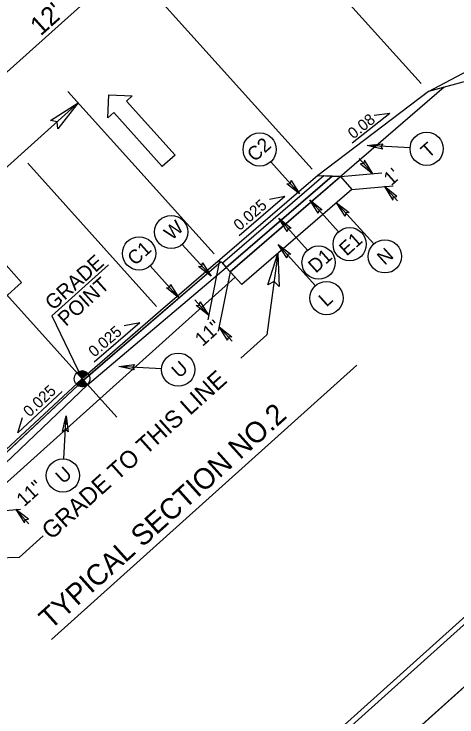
# Model space of a CAD drawing. Extents: x 2488411 to 2488707, y 383669 to 383962.
# Drawn here: x 2488617.46 to 2488643.06, y 383804.17 to 383844.82 of the extents above; entities that cross this region are included whole.
import ezdxf

# ---------------------------------------------------------------- set-up
doc = ezdxf.new("R2010")
doc.units = 0
for name, color, linetype in [('Old_Level_19', 7, 'Continuous'), ('Old_Level_21', 7, 'Continuous'), ('Old_Level_44', 7, 'Continuous'), ('Prop Dimension', 7, 'Continuous'), ('Prop DSN Text', 7, 'Continuous'), ('Prop Paint Stripe', 7, 'Continuous'), ('Prop Rip Rap Related Quantities Text', 7, 'Continuous'), ('Prop Roadway Profile Bench Mark Info Text', 7, 'Continuous'), ('Prop ROW RW Lines', 7, 'Continuous'), ('Prop XS SE Text', 7, 'Continuous'), ('Sheet Cutting Line CELL', 7, 'Continuous'), ('Sheet Data Field CELL', 7, 'Continuous'), ('Sheet Data Text CELL', 7, 'Continuous'), ('Sheet Plan CELL', 7, 'Continuous'), ('Sheet Sticker Incomplete CELL', 7, 'Continuous'), ('Sheet Sticker Preliminary CELL', 7, 'Continuous'), ('Sheet Symbology CELL', 7, 'Continuous'), ('Sheet Title CELL', 7, 'Continuous'), ('Typical Terminator CELL', 7, 'Continuous'), ('Typical Text Centerline CELL', 7, 'Continuous'), ('Typical Text ID Circle CELL', 7, 'Continuous')]:
    doc.layers.add(name, color=color, linetype=linetype)

msp = doc.modelspace()

# ---------------------------------------------------------------- linework, layer by layer
at = {"layer": 'Old_Level_19'}
msp.add_lwpolyline([(2488619.231, 383961.604), (2488468.948, 383826.508), (2488557.194, 383728.341), (2488707.477, 383863.438)], close=True, dxfattribs=at)
at = {"layer": 'Old_Level_21'}
msp.add_lwpolyline([(2488620.631, 383959.24), (2488471.909, 383825.547), (2488556.553, 383731.388), (2488705.275, 383865.081)], close=True, dxfattribs=at)
at = {"layer": 'Prop Dimension'}
for p, q in [((2488632.709, 383830.977), (2488632.073, 383826.262)), ((2488619.64, 383827.369), (2488622.913, 383830.311)), ((2488619.64, 383827.369), (2488621.392, 383823.728)), ((2488630.578, 383824.919), (2488632.073, 383826.262)), ((2488617.748, 383813.385), (2488619.151, 383814.647)), ((2488617.748, 383813.385), (2488612.992, 383813.253))]:
    msp.add_line(p, q, dxfattribs=at)
at = {"layer": 'Prop DSN Text'}
for p, q in [((2488640.35, 383837.081), (2488637.868, 383837.212)), ((2488632.299, 383836.276), (2488633.961, 383834.428)), ((2488636.216, 383832.221), (2488634.554, 383834.069)), ((2488638.253, 383831.522), (2488636.106, 383833.91)), ((2488634.423, 383831.16), (2488632.762, 383833.009)), ((2488627.186, 383831.501), (2488628.847, 383829.653)), ((2488634.879, 383829.11), (2488632.732, 383831.498)), ((2488625.329, 383830.262), (2488626.991, 383828.414)), ((2488625.991, 383824.306), (2488623.509, 383824.437)), ((2488620.335, 383819.093), (2488620.468, 383821.576))]:
    msp.add_line(p, q, dxfattribs=at)
for centre in [(2488631.656, 383836.991), (2488641.31, 383837.029), (2488626.543, 383832.216), (2488636.859, 383831.506), (2488624.687, 383830.977), (2488638.895, 383830.807), (2488635.066, 383830.445), (2488635.521, 383828.395), (2488626.951, 383824.254), (2488620.284, 383818.133)]:
    msp.add_circle(centre, 0.962, dxfattribs=at)
at = {"layer": 'Prop Paint Stripe'}
for points in [[(2488638.758, 383837.01), (2488637.868, 383837.212), (2488638.78, 383837.324), (2488638.657, 383837.17)], [(2488637.484, 383836.153), (2488638.201, 383835.587), (2488637.715, 383836.367), (2488637.673, 383836.175)], [(2488633.474, 383835.201), (2488633.961, 383834.428), (2488633.237, 383834.994), (2488633.433, 383835.015)], [(2488639.586, 383834.278), (2488638.869, 383834.844), (2488639.355, 383834.064), (2488639.398, 383834.256)], [(2488635.041, 383833.296), (2488634.554, 383834.069), (2488635.278, 383833.503), (2488635.082, 383833.482)], [(2488636.592, 383833.137), (2488636.106, 383833.91), (2488636.83, 383833.344), (2488636.634, 383833.323)], [(2488633.248, 383832.236), (2488632.762, 383833.009), (2488633.486, 383832.442), (2488633.29, 383832.421)], [(2488633.218, 383830.725), (2488632.732, 383831.498), (2488633.456, 383830.932), (2488633.26, 383830.911)], [(2488628.361, 383830.426), (2488628.847, 383829.653), (2488628.123, 383830.219), (2488628.319, 383830.24)], [(2488626.505, 383829.187), (2488626.991, 383828.414), (2488626.267, 383828.98), (2488626.463, 383829.002)], [(2488628.222, 383828.173), (2488628.709, 383827.4), (2488627.985, 383827.966), (2488628.18, 383827.988)], [(2488629.803, 383825.951), (2488629.317, 383826.723), (2488630.041, 383826.157), (2488629.845, 383826.136)], [(2488624.4, 383824.235), (2488623.509, 383824.437), (2488624.421, 383824.549), (2488624.298, 383824.396)], [(2488620.265, 383820.685), (2488620.468, 383821.576), (2488620.579, 383820.663), (2488620.426, 383820.787)], [(2488618.289, 383815.6), (2488617.572, 383816.166), (2488618.058, 383815.386), (2488618.101, 383815.578)]]:
    msp.add_lwpolyline(points, close=True, dxfattribs=at)
at = {"layer": 'Prop Rip Rap Related Quantities Text'}
for p, q in [((2488642.314, 383840.591), (2488629.949, 383829.915)), ((2488635.013, 383835.489), (2488625.932, 383827.648)), ((2488635.373, 383835.47), (2488629.508, 383830.406)), ((2488635.849, 383835.445), (2488629.729, 383830.16)), ((2488635.013, 383835.489), (2488636.325, 383835.42)), ((2488636.325, 383835.42), (2488636.993, 383834.676)), ((2488636.993, 383834.676), (2488630.618, 383829.171)), ((2488629.424, 383830.499), (2488621.473, 383823.634)), ((2488629.729, 383830.16), (2488629.424, 383830.499)), ((2488629.949, 383829.915), (2488630.618, 383829.171)), ((2488625.932, 383827.648), (2488621.392, 383823.728)), ((2488613.805, 383816.458), (2488621.477, 383823.637)), ((2488617.012, 383819.63), (2488621.392, 383823.728))]:
    msp.add_line(p, q, dxfattribs=at)
at = {"layer": 'Prop Roadway Profile Bench Mark Info Text'}
for p, q in [((2488639.183, 383839.079), (2488637.001, 383837.35)), ((2488639.183, 383839.079), (2488638.278, 383838.946)), ((2488633.117, 383834.277), (2488630.477, 383831.998)), ((2488633.117, 383834.277), (2488632.218, 383834.105)), ((2488624.729, 383826.96), (2488622.089, 383824.682)), ((2488624.729, 383826.96), (2488623.83, 383826.789)), ((2488617.674, 383820.603), (2488620.233, 383822.998)), ((2488617.674, 383820.603), (2488617.94, 383821.479))]:
    msp.add_line(p, q, dxfattribs=at)
at = {"layer": 'Prop ROW RW Lines'}
for p, q in [((2488622.886, 383838.826), (2488622.946, 383840.151)), ((2488622.946, 383840.151), (2488624.291, 383840.09)), ((2488624.291, 383840.09), (2488623.957, 383839.789)), ((2488623.957, 383839.789), (2488626.764, 383836.665)), ((2488623.22, 383839.127), (2488622.886, 383838.826)), ((2488626.028, 383836.004), (2488623.22, 383839.127)), ((2488626.764, 383836.665), (2488626.028, 383836.004)), ((2488617.895, 383829.288), (2488617.004, 383830.302)), ((2488616.904, 383828.416), (2488617.895, 383829.288))]:
    msp.add_line(p, q, dxfattribs=at)
at = {"layer": 'Prop XS SE Text'}
msp.add_line((2488557.194, 383728.341), (2488707.477, 383863.438), dxfattribs=at)
at = {"layer": 'Sheet Cutting Line CELL'}
msp.add_lwpolyline([(2488619.72, 383958.009), (2488485.857, 383837.674), (2488570.092, 383743.97), (2488703.955, 383864.305)], close=True, dxfattribs=at)
at = {"layer": 'Sheet Data Field CELL'}
for p, q in [((2488635.373, 383835.47), (2488629.508, 383830.406)), ((2488629.729, 383830.16), (2488635.849, 383835.445)), ((2488635.849, 383835.445), (2488635.373, 383835.47)), ((2488629.508, 383830.406), (2488629.729, 383830.16))]:
    msp.add_line(p, q, dxfattribs=at)
at = {"layer": 'Sheet Data Text CELL'}
msp.add_line((2488619.617, 383808.643), (2488637.267, 383824.51), dxfattribs=at)
at = {"layer": 'Sheet Plan CELL'}
for p, q in [((2488641.407, 383840.341), (2488648.692, 383844.202)), ((2488653.851, 383843.766), (2488641.407, 383840.341))]:
    msp.add_line(p, q, dxfattribs=at)
at = {"layer": 'Sheet Sticker Incomplete CELL'}
msp.add_line((2488641.407, 383840.341), (2488635.013, 383835.489), dxfattribs=at)
at = {"layer": 'Sheet Sticker Preliminary CELL'}
for points in [[(2488619.558, 383838.671), (2488621.168, 383839.684), (2488619.988, 383838.176), (2488619.944, 383838.584)], [(2488638.331, 383837.107), (2488637.868, 383837.212), (2488638.343, 383837.271), (2488638.278, 383837.19)], [(2488633.707, 383834.83), (2488633.961, 383834.428), (2488633.584, 383834.723), (2488633.686, 383834.734)], [(2488634.808, 383833.667), (2488634.554, 383834.069), (2488634.931, 383833.775), (2488634.829, 383833.763)], [(2488633.015, 383832.606), (2488632.762, 383833.009), (2488633.139, 383832.714), (2488633.037, 383832.703)], [(2488632.138, 383829.162), (2488632.709, 383830.977), (2488632.787, 383829.064), (2488632.489, 383829.346)], [(2488628.594, 383830.055), (2488628.847, 383829.653), (2488628.47, 383829.948), (2488628.572, 383829.959)], [(2488626.738, 383828.817), (2488626.991, 383828.414), (2488626.614, 383828.709), (2488626.716, 383828.72)], [(2488623.973, 383824.332), (2488623.509, 383824.437), (2488623.984, 383824.496), (2488623.92, 383824.416)], [(2488620.362, 383821.112), (2488620.468, 383821.576), (2488620.526, 383821.101), (2488620.446, 383821.165)]]:
    msp.add_lwpolyline(points, close=True, dxfattribs=at)
at = {"layer": 'Sheet Symbology CELL'}
for p, q in [((2488635.849, 383835.445), (2488629.729, 383830.16)), ((2488632.911, 383832.472), (2488636.325, 383835.42)), ((2488636.325, 383835.42), (2488635.849, 383835.445)), ((2488629.949, 383829.915), (2488632.911, 383832.472)), ((2488632.911, 383832.472), (2488632.911, 383832.472)), ((2488629.729, 383830.16), (2488629.424, 383830.499)), ((2488629.424, 383830.499), (2488629.424, 383830.499)), ((2488621.702, 383823.383), (2488629.729, 383830.16)), ((2488629.729, 383830.16), (2488629.949, 383829.915)), ((2488614.111, 383816.121), (2488621.702, 383823.383))]:
    msp.add_line(p, q, dxfattribs=at)
for points in [[(2488632.911, 383832.472), (2488632.911, 383832.472)], [(2488629.424, 383830.499), (2488621.477, 383823.637), (2488621.559, 383823.543)], [(2488621.559, 383823.543), (2488621.477, 383823.637), (2488613.805, 383816.458)]]:
    msp.add_lwpolyline(points, dxfattribs=at)
at = {"layer": 'Sheet Title CELL'}
for p, q in [((2488640.989, 383840.807), (2488629.385, 383853.715)), ((2488591.299, 383818.326), (2488629.958, 383853.078)), ((2488634.692, 383835.847), (2488621.618, 383850.39)), ((2488629.023, 383830.945), (2488620.574, 383840.344)), ((2488605.55, 383825.645), (2488621.168, 383839.684)), ((2488638.201, 383835.587), (2488637.406, 383836.472)), ((2488625.694, 383827.913), (2488618.251, 383836.192)), ((2488636.325, 383835.42), (2488638.714, 383835.633)), ((2488636.993, 383834.676), (2488639.383, 383834.89)), ((2488639.616, 383834.013), (2488638.869, 383834.844)), ((2488629.341, 383830.592), (2488628.655, 383827.127)), ((2488629.949, 383829.915), (2488629.267, 383826.471)), ((2488628.709, 383827.4), (2488627.913, 383828.285)), ((2488630.064, 383825.892), (2488629.317, 383826.723)), ((2488614.332, 383815.876), (2488617.829, 383816.189)), ((2488618.32, 383815.335), (2488617.572, 383816.166))]:
    msp.add_line(p, q, dxfattribs=at)
at = {"layer": 'Typical Terminator CELL'}
msp.add_line((2488623.395, 383821.5), (2488613.727, 383832.255), dxfattribs=at)
at = {"layer": 'Typical Text Centerline CELL'}
for p, q in [((2488621.093, 383824.062), (2488621.392, 383823.728)), ((2488621.392, 383823.728), (2488621.093, 383824.062)), ((2488621.725, 383824.028), (2488621.392, 383823.728)), ((2488621.059, 383823.429), (2488621.392, 383823.728)), ((2488621.392, 383823.728), (2488621.691, 383823.396))]:
    msp.add_line(p, q, dxfattribs=at)
for points in [[(2488621.397, 383823.733), (2488621.098, 383824.066), (2488621.098, 383824.066)], [(2488621.403, 383823.739), (2488621.104, 383824.072)], [(2488621.41, 383823.745), (2488621.112, 383824.077)], [(2488621.417, 383823.751), (2488621.118, 383824.083)], [(2488621.423, 383823.757), (2488621.126, 383824.088)], [(2488621.43, 383823.763), (2488621.133, 383824.094)], [(2488621.437, 383823.769), (2488621.14, 383824.099)], [(2488621.443, 383823.775), (2488621.148, 383824.103)], [(2488621.45, 383823.781), (2488621.156, 383824.109)], [(2488621.457, 383823.787), (2488621.163, 383824.113)], [(2488621.463, 383823.793), (2488621.171, 383824.118)], [(2488621.47, 383823.799), (2488621.179, 383824.122)], [(2488621.477, 383823.805), (2488621.187, 383824.127)], [(2488621.483, 383823.811), (2488621.196, 383824.13)], [(2488621.49, 383823.817), (2488621.204, 383824.135)], [(2488621.497, 383823.823), (2488621.213, 383824.139)], [(2488621.503, 383823.829), (2488621.221, 383824.142)], [(2488621.51, 383823.835), (2488621.23, 383824.146)], [(2488621.517, 383823.841), (2488621.239, 383824.149)], [(2488621.523, 383823.847), (2488621.249, 383824.152)], [(2488621.53, 383823.853), (2488621.258, 383824.155)], [(2488621.537, 383823.859), (2488621.267, 383824.158)], [(2488621.543, 383823.865), (2488621.277, 383824.161)], [(2488621.55, 383823.871), (2488621.287, 383824.164)], [(2488621.557, 383823.877), (2488621.297, 383824.166)], [(2488621.563, 383823.883), (2488621.307, 383824.168)], [(2488621.57, 383823.889), (2488621.317, 383824.17)], [(2488621.577, 383823.895), (2488621.328, 383824.171)], [(2488621.583, 383823.901), (2488621.339, 383824.173)], [(2488621.59, 383823.907), (2488621.349, 383824.174)], [(2488621.597, 383823.913), (2488621.36, 383824.175)], [(2488621.603, 383823.919), (2488621.372, 383824.176)], [(2488621.61, 383823.925), (2488621.384, 383824.176)], [(2488621.616, 383823.931), (2488621.396, 383824.176)], [(2488621.623, 383823.937), (2488621.408, 383824.176)], [(2488621.63, 383823.943), (2488621.42, 383824.176)], [(2488621.636, 383823.949), (2488621.434, 383824.174)], [(2488621.643, 383823.955), (2488621.447, 383824.173)], [(2488621.65, 383823.961), (2488621.461, 383824.171)], [(2488621.656, 383823.966), (2488621.475, 383824.168)], [(2488621.663, 383823.972), (2488621.49, 383824.166)], [(2488621.67, 383823.978), (2488621.505, 383824.162)], [(2488621.676, 383823.984), (2488621.521, 383824.158)], [(2488621.683, 383823.99), (2488621.538, 383824.152)], [(2488621.69, 383823.996), (2488621.556, 383824.145)], [(2488621.696, 383824.002), (2488621.575, 383824.137)], [(2488621.703, 383824.008), (2488621.596, 383824.127)], [(2488621.71, 383824.014), (2488621.621, 383824.113)], [(2488621.716, 383824.02), (2488621.649, 383824.096)], [(2488621.723, 383824.026), (2488621.69, 383824.063)], [(2488621.105, 383823.385), (2488621.062, 383823.433)], [(2488621.142, 383823.357), (2488621.069, 383823.439)], [(2488621.17, 383823.34), (2488621.076, 383823.445)], [(2488621.193, 383823.328), (2488621.082, 383823.451)], [(2488621.213, 383823.318), (2488621.089, 383823.456)], [(2488621.233, 383823.31), (2488621.096, 383823.462)], [(2488621.25, 383823.304), (2488621.102, 383823.468)], [(2488621.267, 383823.299), (2488621.109, 383823.474)], [(2488621.283, 383823.295), (2488621.116, 383823.48)], [(2488621.298, 383823.291), (2488621.122, 383823.486)], [(2488621.313, 383823.288), (2488621.129, 383823.492)], [(2488621.327, 383823.286), (2488621.136, 383823.498)], [(2488621.341, 383823.284), (2488621.142, 383823.504)], [(2488621.354, 383823.283), (2488621.149, 383823.51)], [(2488621.366, 383823.282), (2488621.156, 383823.516)], [(2488621.379, 383823.281), (2488621.162, 383823.522)], [(2488621.391, 383823.281), (2488621.169, 383823.528)], [(2488621.403, 383823.281), (2488621.176, 383823.534)], [(2488621.415, 383823.281), (2488621.182, 383823.54)], [(2488621.426, 383823.282), (2488621.189, 383823.546)], [(2488621.437, 383823.284), (2488621.196, 383823.552)], [(2488621.448, 383823.285), (2488621.202, 383823.558)], [(2488621.459, 383823.286), (2488621.209, 383823.564)], [(2488621.47, 383823.288), (2488621.216, 383823.57)], [(2488621.48, 383823.29), (2488621.222, 383823.576)], [(2488621.49, 383823.292), (2488621.229, 383823.582)], [(2488621.5, 383823.294), (2488621.236, 383823.588)], [(2488621.51, 383823.297), (2488621.242, 383823.594)], [(2488621.519, 383823.3), (2488621.249, 383823.6)], [(2488621.528, 383823.303), (2488621.256, 383823.606)], [(2488621.537, 383823.306), (2488621.262, 383823.612)], [(2488621.547, 383823.309), (2488621.269, 383823.618)], [(2488621.556, 383823.312), (2488621.276, 383823.624)], [(2488621.565, 383823.316), (2488621.282, 383823.63)], [(2488621.573, 383823.319), (2488621.289, 383823.636)], [(2488621.582, 383823.323), (2488621.295, 383823.642)], [(2488621.59, 383823.328), (2488621.302, 383823.648)], [(2488621.599, 383823.331), (2488621.309, 383823.654)], [(2488621.607, 383823.336), (2488621.315, 383823.66)], [(2488621.615, 383823.34), (2488621.322, 383823.666)], [(2488621.623, 383823.345), (2488621.329, 383823.672)], [(2488621.631, 383823.349), (2488621.335, 383823.678)], [(2488621.638, 383823.355), (2488621.342, 383823.684)], [(2488621.645, 383823.36), (2488621.349, 383823.69)], [(2488621.653, 383823.365), (2488621.355, 383823.696)], [(2488621.66, 383823.37), (2488621.362, 383823.702)], [(2488621.667, 383823.376), (2488621.369, 383823.708)], [(2488621.674, 383823.382), (2488621.375, 383823.714)], [(2488621.681, 383823.387), (2488621.382, 383823.72)], [(2488621.688, 383823.393), (2488621.688, 383823.393), (2488621.389, 383823.726)]]:
    msp.add_lwpolyline(points, dxfattribs=at)
msp.add_circle((2488621.392, 383823.729), 0.448, dxfattribs=at)
for start, end in [(41.9443, 131.9443), (221.9443, 311.9443)]:
    msp.add_arc((2488621.392, 383823.729), 0.448, start, end, dxfattribs=at)
at = {"layer": 'Typical Text ID Circle CELL'}
for p, q in [((2488621.702, 383823.383), (2488629.729, 383830.16)), ((2488630.234, 383829.598), (2488629.729, 383830.16)), ((2488614.617, 383815.559), (2488630.234, 383829.598)), ((2488614.111, 383816.121), (2488621.702, 383823.383))]:
    msp.add_line(p, q, dxfattribs=at)

# ---------------------------------------------------------------- texts
at = {"layer": 'Old_Level_44'}
for s, p in [('C2', (2488631.371, 383836.235)), ('T', (2488641.413, 383836.445)), ('W', (2488626.574, 383831.699)), ('E1', (2488636.689, 383830.788)), ('C1', (2488624.453, 383830.235)), ('D1', (2488634.901, 383829.799)), ('N', (2488638.888, 383830.257)), ('L', (2488635.514, 383827.845)), ('U', (2488627.008, 383823.718)), ('U', (2488620.298, 383817.604))]:
    msp.add_text(s, height=0.8, rotation=41.9538, dxfattribs=at).set_placement(p)
at = {"layer": 'Prop Dimension'}
for s, height, p in [('GRADE', 0.85, (2488619.718, 383827.642)), ('POINT', 0.85, (2488620.457, 383826.721)), ('GRADE TO THIS LINE', 1, (2488619.617, 383814.367))]:
    msp.add_text(s, height=height, rotation=41.9538, dxfattribs=at).set_placement(p)
at = {"layer": 'Prop Roadway Profile Bench Mark Info Text'}
for s, rotation, p in [('0.08', 38.4053, (2488637.074, 383837.562)), ('0.025', 40.8081, (2488630.493, 383832.258)), ('0.025', 40.8081, (2488622.104, 383824.942)), ('0.025', 43.0996, (2488618.357, 383821.477))]:
    msp.add_text(s, height=0.6476, rotation=rotation, dxfattribs=at).set_placement(p)
at = {"layer": 'Sheet Data Text CELL'}
msp.add_text('TYPICAL SECTION NO.2  ', height=1.2, rotation=41.9538, dxfattribs=at).set_placement((2488619.576, 383809.174))
at = {"layer": 'Sheet Title CELL'}
for s, height, p in [("12'", 1.0817, (2488618.995, 383843.517)), ("1'", 0.8, (2488639.263, 383834.852)), ('11"', 0.8, (2488628.354, 383825.56)), ('11"', 0.8, (2488618.04, 383816.288))]:
    msp.add_text(s, height=height, rotation=41.9538, dxfattribs=at).set_placement(p)

doc.saveas('drawing.dxf')
